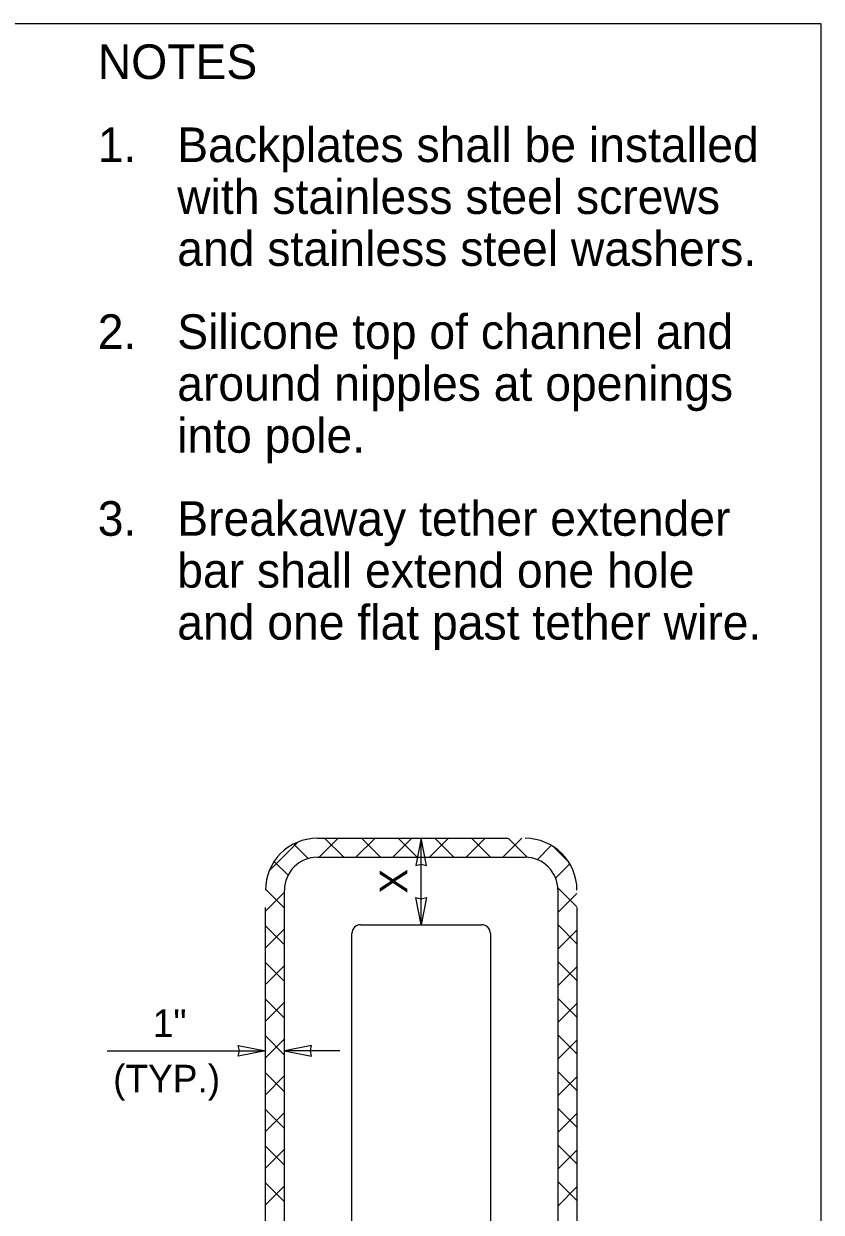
# Model space of a CAD drawing. Extents: x 99862 to 104211, y 98939 to 102076.
# Drawn here: x 102690 to 103151, y 101389 to 102076 of the extents above; entities that cross this region are included whole.
import ezdxf

# ---------------------------------------------------------------- set-up
doc = ezdxf.new("R2010")
doc.units = 0
for name, color, linetype in [('Level 1', 7, 'Continuous'), ('Level 15', 7, 'Continuous'), ('Level 20', 7, 'Continuous'), ('Level 34', 7, 'Continuous'), ('Level 60', 7, 'Continuous')]:
    doc.layers.add(name, color=color, linetype=linetype)

msp = doc.modelspace()

# ---------------------------------------------------------------- linework, layer by layer
at = {"layer": 'Level 1'}
msp.add_lwpolyline([(99862, 99999.5), (103151, 99999.5), (103151, 102075.5), (99862, 102075.5)], close=True, dxfattribs=at)
at = {"layer": 'Level 15'}
for p, q in [((102919.88, 101554.73), (102919.88, 101604.73)), ((102738.43, 101481.81), (102829.88, 101481.81)), ((102872.88, 101481.81), (102840.88, 101481.81))]:
    msp.add_line(p, q, dxfattribs=at)
for points in [[(102919.88, 101604.73), (102916.79, 101589), (102919.88, 101589.73), (102922.96, 101589)], [(102919.88, 101554.73), (102916.79, 101570.45), (102919.88, 101569.72), (102922.96, 101570.45)], [(102829.88, 101481.81), (102814.15, 101478.72), (102814.88, 101481.81), (102814.15, 101484.89)], [(102840.88, 101481.81), (102856.6, 101478.72), (102855.87, 101481.81), (102856.6, 101484.89)]]:
    msp.add_lwpolyline(points, close=True, dxfattribs=at)
at = {"layer": 'Level 34'}
for p, q in [((102832.19, 101586.13), (102848.52, 101602.46)), ((102846.3, 101601.32), (102854.63, 101592.99)), ((102859.88, 101604.73), (102869.88, 101604.73)), ((102861, 101593.73), (102872, 101604.73)), ((102864.11, 101604.73), (102875.11, 101593.73)), ((102869.88, 101604.73), (102969.88, 101604.73)), ((102882.21, 101593.73), (102893.21, 101604.73)), ((102885.32, 101604.73), (102896.32, 101593.73)), ((102903.43, 101593.73), (102914.43, 101604.73)), ((102906.53, 101604.73), (102917.53, 101593.73)), ((102924.64, 101593.73), (102935.64, 101604.73)), ((102927.75, 101604.73), (102938.75, 101593.73)), ((102945.85, 101593.73), (102956.85, 101604.73)), ((102948.96, 101604.73), (102959.96, 101593.73)), ((102967.07, 101593.73), (102978.07, 101604.73)), ((102970.17, 101604.73), (102981.22, 101593.68)), ((102986.92, 101592.37), (102995.05, 101600.5)), ((102859.88, 101593.73), (102979.88, 101593.73)), ((102996.36, 101599.76), (103004.87, 101591.24)), ((102835, 101591.4), (102842.98, 101583.42)), ((102997.53, 101581.76), (103005.62, 101589.86)), ((102829.88, 101562.61), (102840.88, 101573.61)), ((102829.92, 101575.27), (102840.88, 101564.32)), ((102840.88, 101134.73), (102840.88, 101574.73)), ((102998.83, 101576.07), (103009.88, 101565.02)), ((102998.88, 101574.73), (102998.88, 101134.73)), ((102998.88, 101561.9), (103009.88, 101572.9)), ((102829.88, 101434.73), (102829.88, 101564.73)), ((103009.88, 101564.73), (103009.88, 101434.73)), ((102829.88, 101554.1), (102840.88, 101543.1)), ((102829.88, 101541.39), (102840.88, 101552.39)), ((102884.88, 101554.73), (102954.88, 101554.73)), ((102998.88, 101554.81), (103009.88, 101543.81)), ((102879.88, 101159.73), (102879.88, 101549.73)), ((102959.88, 101549.73), (102959.88, 101159.73)), ((102998.88, 101540.69), (103009.88, 101551.69)), ((102829.88, 101532.89), (102840.88, 101521.89)), ((102829.88, 101520.18), (102840.88, 101531.18)), ((102998.88, 101533.59), (103009.88, 101522.59)), ((102998.88, 101519.47), (103009.88, 101530.47)), ((102829.88, 101511.68), (102840.88, 101500.68)), ((102998.88, 101512.38), (103009.88, 101501.38)), ((102829.88, 101498.97), (102840.88, 101509.97)), ((102998.88, 101498.26), (103009.88, 101509.26)), ((102829.88, 101490.46), (102840.88, 101479.46)), ((102998.88, 101491.17), (103009.88, 101480.17)), ((102829.88, 101477.75), (102840.88, 101488.75)), ((102998.88, 101477.05), (103009.88, 101488.05)), ((102998.88, 101469.96), (103009.88, 101458.96)), ((102829.88, 101469.25), (102840.88, 101458.25)), ((102829.88, 101456.54), (102840.88, 101467.54)), ((102998.88, 101455.83), (103009.88, 101466.83)), ((102998.88, 101448.74), (103009.88, 101437.74)), ((102829.88, 101448.04), (102840.88, 101437.04)), ((102829.88, 101435.33), (102840.88, 101446.33)), ((102998.88, 101434.62), (103009.88, 101445.62)), ((102829.88, 101274.73), (102829.88, 101434.73)), ((103009.88, 101434.73), (103009.88, 101274.73)), ((102829.88, 101426.82), (102840.88, 101415.82)), ((102829.88, 101414.11), (102840.88, 101425.11)), ((102998.88, 101427.53), (103009.88, 101416.53)), ((102998.88, 101413.41), (103009.88, 101424.41)), ((102829.88, 101405.61), (102840.88, 101394.61)), ((102829.88, 101392.9), (102840.88, 101403.9)), ((102998.88, 101406.32), (103009.88, 101395.32)), ((102998.88, 101392.19), (103009.88, 101403.19))]:
    msp.add_line(p, q, dxfattribs=at)
for centre, radius, start, end in [((102859.88, 101574.73), 30, 90, 180), ((102979.88, 101574.73), 30, 360, 90), ((102859.88, 101574.73), 19, 90, 180), ((102979.88, 101574.73), 19, 0, 90), ((102884.88, 101549.73), 5, 90, 180), ((102954.88, 101549.73), 5, 0, 90)]:
    msp.add_arc(centre, radius, start, end, dxfattribs=at)
at = {"layer": 'Level 60'}
msp.add_line((103151, 102075.5), (103151, 102075.5), dxfattribs=at)

# ---------------------------------------------------------------- texts
at = {"layer": 'Level 20'}
for s, height, p in [('NOTES', 20, (102733.01, 102043.57)), ('1.', 20, (102733.01, 101995.57)), ('Backplates shall be installed', 20, (102778.92, 101995.57)), ('with stainless steel screws ', 20, (102778.92, 101965.57)), ('and stainless steel washers.', 20, (102778.92, 101935.57)), ('2.', 20, (102733.01, 101887.57)), ('Silicone top of channel and ', 20, (102778.92, 101887.57)), ('around nipples at openings ', 20, (102778.92, 101857.57)), ('into pole.', 20, (102778.92, 101827.57)), ('3.', 20, (102733.01, 101779.57)), ('Breakaway tether extender', 20, (102778.92, 101779.57)), ('bar shall extend one hole ', 20, (102778.92, 101749.57)), ('and one flat past tether wire.', 20, (102778.92, 101719.57)), ('1"', 16, (102764.8, 101489.81)), ('(TYP.)', 16, (102741.9, 101457.81))]:
    msp.add_text(s, height=height, dxfattribs=at).set_placement(p)
msp.add_text('X', height=16, rotation=90, dxfattribs=at).set_placement((102911.88, 101572.78))

doc.saveas('drawing.dxf')
